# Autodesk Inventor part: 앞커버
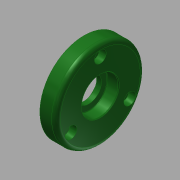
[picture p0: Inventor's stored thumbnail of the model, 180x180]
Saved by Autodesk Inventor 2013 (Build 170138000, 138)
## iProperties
Created: 2015-11
Part Number: 앞커버
Material: 알루미늄 6061
Document SubType Name: Modeling
Designer: mduedu
Density: 1 g/cm^3
Author: mduedu
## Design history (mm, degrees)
sketch "스케치5"
  geometry: C1 r 30 at (0, 0); 2 further points
  constraints: 2 coincident, 1 centre point
  dimensions: "d66" = 60 diameter of C1
extrude "돌출2" new body sketch "스케치5" distance "d67" = 11; taper "d68" = 0 deg
sketch "스케치6"
  geometry: C1 r 16 at (0, 0); 1 further point
  constraints: 1 centre point, 1 coincident
  dimensions: "d69" = 32 diameter of C1
extrude "돌출3" join sketch "스케치6" distance "d70" = 3; taper "d71" = 0 deg
hole "구멍7" diameter "d98" = 25; stored, may be unused: countersink angle "d102" = 90 deg, drill point angle "d104" = 0 deg; dims "d96" = 10, "d97" = 10, "d99" = 6, "d100" = 4, "d101" = 2, "d103" = 3
hole "구멍8" diameter "d107" = 25; stored, may be unused: countersink angle "d111" = 90 deg, drill point angle "d113" = 0 deg; dims "d105" = 10, "d106" = 10, "d108" = 6, "d109" = 4, "d110" = 2, "d112" = 7.7
hole "구멍9" diameter "d116" = 17; stored, may be unused: countersink angle "d120" = 90 deg, drill point angle "d122" = 0 deg; dims "d114" = 10, "d115" = 10, "d117" = 6, "d118" = 4, "d119" = 2, "d121" = 7.7
chamfer "모따기2" distance "d123" = 0.6; stored, may be unused: second distance "d124" = 2, angle "d125" = 30 deg
fillet "모깎기11" dims "d126" = 0.3
fillet "모깎기13" dims "d128" = 3
fillet "모깎기14" dims "d129" = 3
fillet "모깎기15" dims "d130" = 0.3
sketch "스케치8" dims "d131" = 46
  geometry: 3 further points
  constraints: 2 vertical alignment, 1 coincident, 2 other
hole "구멍10" sketch "스케치8" at (0, 23) diameter "d132" = 4.5; stored, may be unused: countersink angle "d136" = 90 deg, drill point angle "d138" = 0 deg; dims "d133" = 6, "d134" = 8, "d135" = 4.6, "d137" = 7.7
node "솔리드2"
pattern_circular "원형 패턴4" dims angle "d140" = 360 deg
